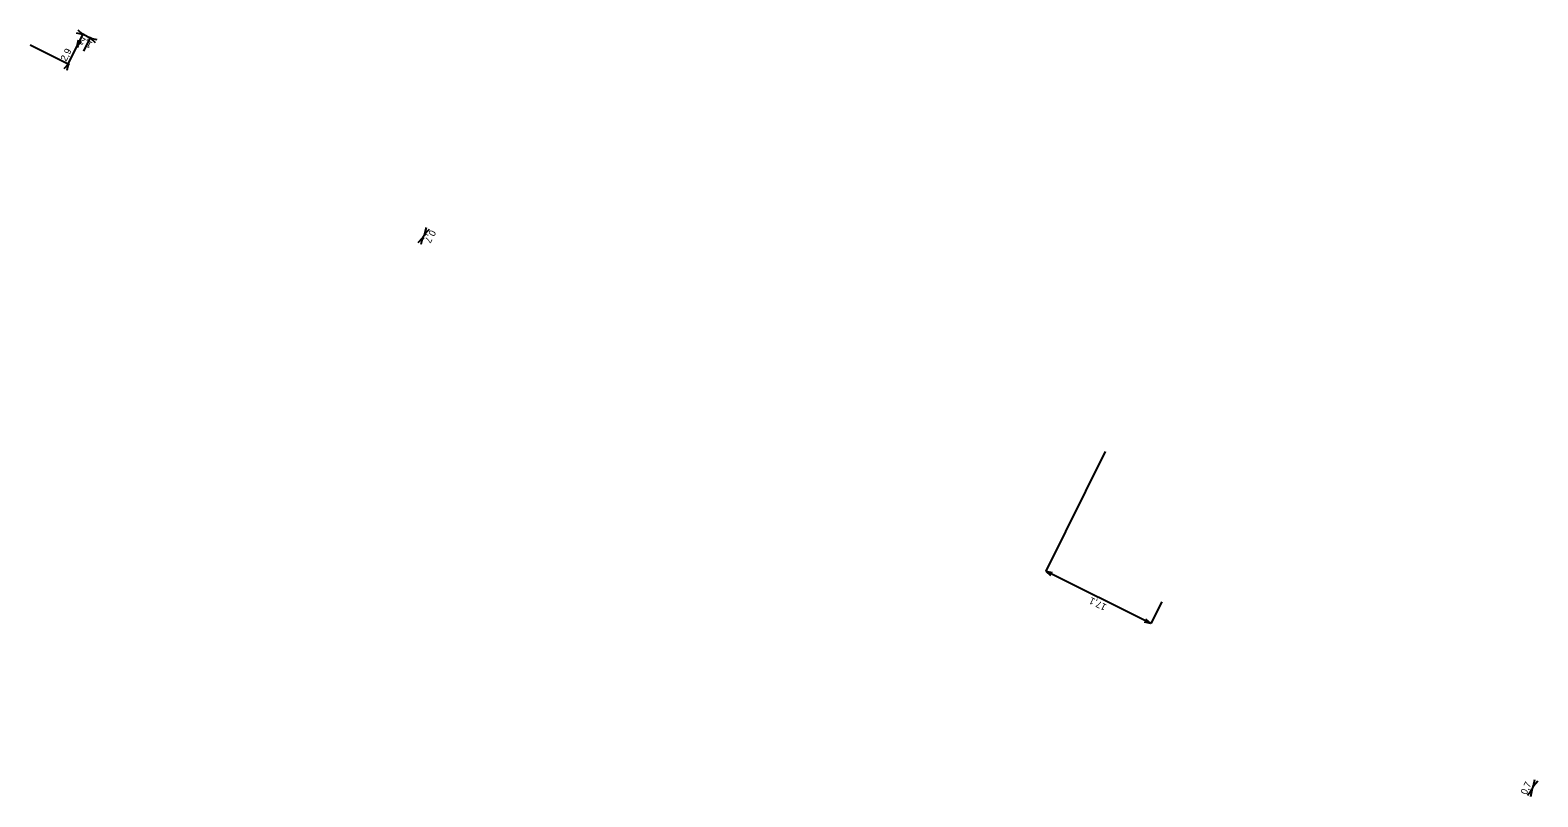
# Model space of a CAD drawing. Extents: x -739255 to -739035, y -1041334 to -1041222.
import ezdxf

# ---------------------------------------------------------------- set-up
doc = ezdxf.new("R2010")
doc.units = 0
doc.layers.add('Kota_VN', color=7, linetype='Continuous')

msp = doc.modelspace()

# ---------------------------------------------------------------- linework, layer by layer
at = {"layer": 'Kota_VN'}
for p, q in [((-739247.56, -1041222.77), (-739248.5, -1041222.58)), ((-739248.4, -1041224.46), (-739247.46, -1041222.59)), ((-739247.56, -1041222.77), (-739248.27, -1041222.13)), ((-739255.27, -1041224.25), (-739249.54, -1041227.16)), ((-739249.81, -1041227.25), (-739248.31, -1041224.29)), ((-739248.44, -1041224.45), (-739248.22, -1041224.56)), ((-739248.4, -1041224.47), (-739248.2, -1041223.53)), ((-739248.4, -1041224.47), (-739247.76, -1041223.76)), ((-739246.31, -1041223.39), (-739247.73, -1041222.68)), ((-739247.43, -1041225.2), (-739246.4, -1041223.12)), ((-739246.48, -1041223.3), (-739245.54, -1041223.49)), ((-739246.48, -1041223.3), (-739245.77, -1041223.94)), ((-739249.72, -1041227.07), (-739250.36, -1041227.78)), ((-739249.72, -1041227.07), (-739249.92, -1041228.01)), ((-739197.65, -1041251.83), (-739197.42, -1041250.9)), ((-739197.65, -1041251.83), (-739196.98, -1041251.14)), ((-739197.99, -1041252.44), (-739198.66, -1041253.13)), ((-739197.99, -1041252.44), (-739198.23, -1041253.37)), ((-739197.56, -1041251.65), (-739198.09, -1041252.62)), ((-739198, -1041252.44), (-739197.82, -1041252.54)), ((-739197.66, -1041251.82), (-739197.48, -1041251.93)), ((-739098.32, -1041283.56), (-739107.02, -1041301.04)), ((-739091.67, -1041308.67), (-739107.02, -1041301.04)), ((-739107.02, -1041301.04), (-739106.08, -1041301.23)), ((-739107.02, -1041301.04), (-739106.3, -1041301.67)), ((-739090.08, -1041305.48), (-739091.67, -1041308.67)), ((-739091.67, -1041308.67), (-739092.39, -1041308.04)), ((-739091.67, -1041308.67), (-739092.61, -1041308.48)), ((-739036.16, -1041333.18), (-739035.71, -1041332.18)), ((-739035.78, -1041332.37), (-739035.97, -1041332.28)), ((-739035.79, -1041332.36), (-739035.63, -1041331.42)), ((-739035.79, -1041332.36), (-739035.18, -1041331.62)), ((-739036.08, -1041332.99), (-739036.69, -1041333.74)), ((-739036.07, -1041333), (-739036.26, -1041332.91)), ((-739036.08, -1041332.99), (-739036.23, -1041333.94))]:
    msp.add_line(p, q, dxfattribs=at)

# ---------------------------------------------------------------- texts
for s, rotation, p in [('2,9', 63.0691, (-739250.02, -1041226.77)), ('1,2', 153.4788, (-739246.09, -1041223.95)), ('0,7', 240.9817, (-739196.83, -1041251.17)), ('17,1', 153.5435, (-739098.04, -1041305.95)), ('0,7', 65.556, (-739036.85, -1041333.72))]:
    msp.add_text(s, height=1, rotation=rotation, dxfattribs=at).set_placement(p)

doc.saveas('drawing.dxf')
